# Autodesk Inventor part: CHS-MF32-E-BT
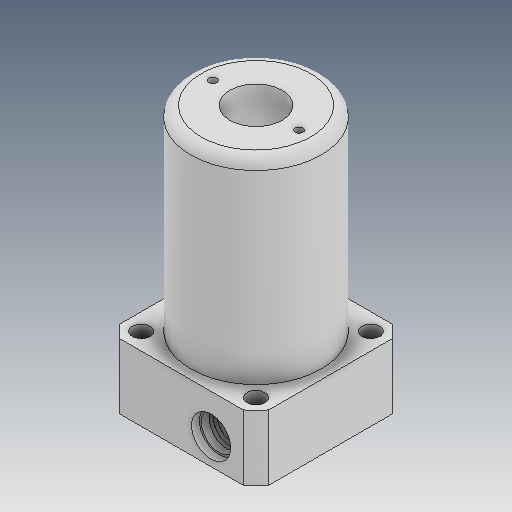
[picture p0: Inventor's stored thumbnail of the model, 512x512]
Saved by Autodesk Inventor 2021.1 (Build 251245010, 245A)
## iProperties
Created: 2021-05
Part Number: CHS-MF32-E-BT
Material: Ogólny
Document SubType Name: Modeling
Designer: user
Density: 1 g/cm^3
Appearance: Domyślna
Author: user
Revision Number: ÈÎºÎ
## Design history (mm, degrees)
feature "Í¹Ì¨-À­Éì1"
node "Bryła1"
